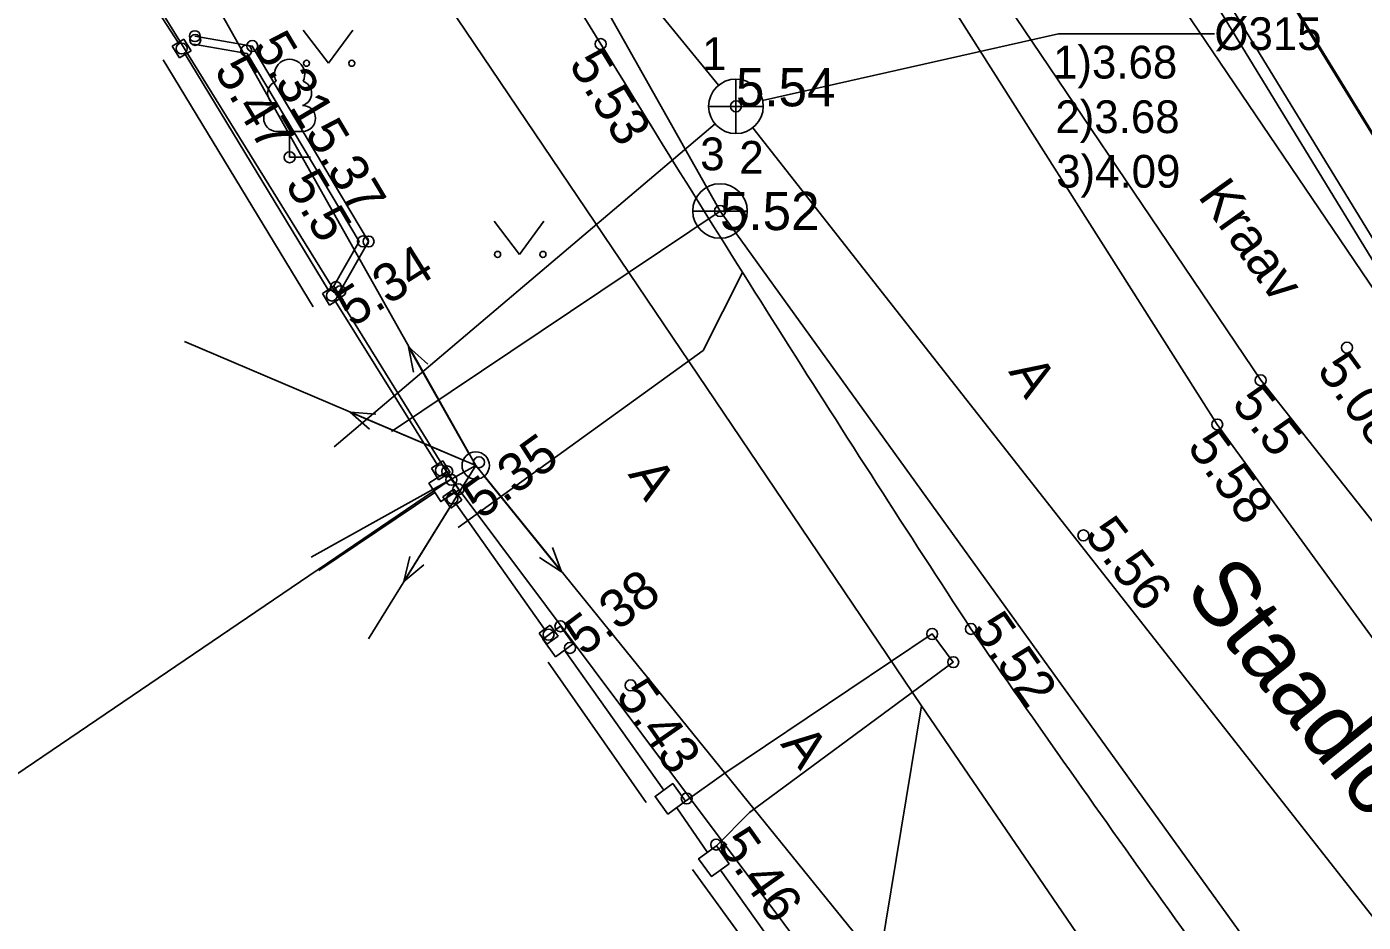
# Model space of a CAD drawing. Extents: x 473307 to 473719, y 6532843 to 6533381.
# Drawn here: x 473422.75 to 473447.22, y 6533044.23 to 6533060.64 of the extents above; entities that cross this region are included whole.
import ezdxf

# ---------------------------------------------------------------- set-up
doc = ezdxf.new("R2010")
doc.units = 0
for name, color, linetype in [('AED', 7, 'Continuous'), ('Default', 7, 'Continuous'), ('HALJASTUS', 7, 'Continuous'), ('KKAEV', 7, 'Continuous'), ('KKAEV_NR', 7, 'Continuous'), ('KORGUS', 7, 'Continuous'), ('KTRASS', 7, 'Continuous'), ('MPKAABEL', 7, 'Continuous'), ('MPOHULIIN', 7, 'Continuous'), ('PIIR', 7, 'Continuous'), ('POST', 7, 'Continuous'), ('PUU', 7, 'Continuous'), ('SITRASS', 7, 'Continuous'), ('TEE', 7, 'Continuous'), ('VEEKOGU', 7, 'Continuous'), ('VKAEV', 7, 'Continuous'), ('VTRASS', 7, 'Continuous')]:
    doc.layers.add(name, color=color, linetype=linetype)

# ---------------------------------------------------------------- blocks, each defined once
blk = doc.blocks.new('KAKAEV')
at = {"layer": 'Default'}
for p, q in [((0, -1), (0, 1)), ((-1, 0), (1, 0))]:
    blk.add_line(p, q, dxfattribs=at)
blk.add_circle((0, 0), 1, dxfattribs=at)
blk = doc.blocks.new('VEKAEV')
at = {"layer": 'Default'}
blk.add_line((-1, 0), (1, 0), dxfattribs=at)
blk.add_circle((0, 0), 1, dxfattribs=at)
blk = doc.blocks.new('PUPOST')
at = {"layer": 'Default'}
blk.add_circle((0, 0), 0.5, dxfattribs=at)
blk = doc.blocks.new('MPSUUN')
at = {"layer": 'Default'}
for p, q in [((0.5, 0), (5, 0)), ((5, 0), (4.097, -0.297)), ((5, 0), (4.098, 0.3))]:
    blk.add_line(p, q, dxfattribs=at)
blk = doc.blocks.new('VARPOS')
at = {"layer": 'Default'}
for p, q in [((-0.25, 0.25), (-0.25, -0.25)), ((-0.25, 0.25), (0.25, 0.25)), ((0.25, 0.25), (0.25, -0.25)), ((-0.25, -0.25), (0.25, -0.25))]:
    blk.add_line(p, q, dxfattribs=at)
blk = doc.blocks.new('LEHTP1')
at = {"layer": 'Default'}
for p, q in [((0.48, 0.95), (-0.48, 0.95)), ((0, 0), (0, 0.95)), ((0.76, 0), (0, 0))]:
    blk.add_line(p, q, dxfattribs=at)
for centre, radius, start, end in [((0, 3.04), 0.554, 332.5799, 207.4201), ((-0.34, 2.345), 0.465, 109.0217, 253.1415), ((0.34, 2.345), 0.465, 286.8508, 70.9859), ((-0.475, 1.425), 0.475, 90.0016, 269.3953), ((0.475, 1.425), 0.475, 270.6047, 89.9984)]:
    blk.add_arc(centre, radius, start, end, dxfattribs=at)
blk = doc.blocks.new('MURU')
at = {"layer": 'Default'}
for p, q in [((-0.927, 1.213), (0, 0)), ((0, 0), (0.891, 1.213))]:
    blk.add_line(p, q, dxfattribs=at)
for centre in [(-0.802, 0), (0.856, 0)]:
    blk.add_circle(centre, 0.11, dxfattribs=at)

msp = doc.modelspace()

# ---------------------------------------------------------------- linework, layer by layer
at = {"layer": 'AED'}
for points in [[(473572.372, 6533059.989), (473562.796, 6533044.25), (473549.715, 6533022.819), (473547.153, 6533018.61), (473538.777, 6533017.059), (473515.614, 6533013.019), (473502.84, 6533010.765), (473486.499, 6533007.9), (473486.322, 6533008.043), (473484.734, 6533009.635), (473455.331, 6533045.745), (473429.609, 6533087.699), (473409.64, 6533128.98), (473398.626, 6533166.806)], [(473425.025, 6533061.109), (473425.519, 6533060.346)], [(473428.268, 6533055.819), (473425.649, 6533060.132)], [(473428.4, 6533055.606), (473430.262, 6533052.618)], [(473430.664, 6533052.156), (473430.447, 6533052.492), (473430.111, 6533052.275), (473430.327, 6533051.939), (473430.664, 6533052.156)], [(473430.219, 6533052.107), (473428.098, 6533050.675)], [(473430.612, 6533051.893), (473432.23, 6533049.604)], [(473432.754, 6533049.332), (473432.52, 6533049.656), (473432.196, 6533049.422), (473432.43, 6533049.098), (473432.754, 6533049.332)], [(473434.415, 6533046.656), (473432.592, 6533049.215)], [(473434.811, 6533046.449), (473434.577, 6533046.773), (473434.253, 6533046.539), (473434.487, 6533046.215), (473434.811, 6533046.449)], [(473434.649, 6533046.332), (473435.214, 6533045.514)], [(473435.61, 6533045.306), (473435.376, 6533045.631), (473435.051, 6533045.397), (473435.285, 6533045.072), (473435.61, 6533045.306)], [(473437.368, 6533042.487), (473435.448, 6533045.189)]]:
    msp.add_lwpolyline(points, dxfattribs=at)
at = {"layer": 'HALJASTUS'}
for points in [[(473427.991, 6533055.504), (473425.242, 6533060.031)], [(473434.087, 6533046.427), (473432.296, 6533048.996)], [(473443.677, 6533033.162), (473434.939, 6533045.198)]]:
    msp.add_lwpolyline(points, dxfattribs=at)
at = {"layer": 'KKAEV_NR'}
msp.add_lwpolyline([(473436.222, 6533059.289), (473441.643, 6533060.51), (473444.495, 6533060.51)], dxfattribs=at)
at = {"layer": 'KORGUS'}
for centre in [(473425.825, 6533060.465), (473425.584, 6533060.239), (473425.832, 6533060.395), (473426.767, 6533060.199), (473426.876, 6533060.284), (473433.257, 6533060.319), (473435.734, 6533059.179), (473427.561, 6533058.246), (473435.442, 6533057.262), (473428.904, 6533056.705), (473429.007, 6533056.703), (473428.408, 6533055.868), (473428.489, 6533055.793), (473428.333, 6533055.712), (473446.923, 6533054.759), (473445.343, 6533054.161), (473444.547, 6533053.352), (473431.029, 6533052.66), (473430.329, 6533052.512), (473430.447, 6533052.492), (473430.522, 6533052.338), (473430.65, 6533052.165), (473430.54, 6533051.995), (473442.097, 6533051.32), (473432.302, 6533049.502), (473432.52, 6533049.656), (473439.327, 6533049.514), (473440.037, 6533049.606), (473432.695, 6533049.259), (473439.714, 6533048.998), (473433.804, 6533048.573), (473434.833, 6533046.501), (473435.371, 6533045.656)]:
    msp.add_circle(centre, 0.1, dxfattribs=at)
at = {"layer": 'KTRASS'}
for p, q in [((473418.47, 6533080.248), (473435.417, 6533059.566)), ((473436.043, 6533058.786), (473462.581, 6533024.994))]:
    msp.add_line(p, q, dxfattribs=at)
msp.add_lwpolyline([(473428.378, 6533052.943), (473435.353, 6533058.856)], dxfattribs=at)
at = {"layer": 'MPKAABEL'}
for points in [[(473481.096, 6533010.082), (473475.299, 6533017.476), (473469.705, 6533025.438), (473464.809, 6533033.306), (473458.878, 6533040.236), (473452.764, 6533048.342), (473452.582, 6533049.145), (473450.829, 6533050.743), (473441.685, 6533065.704), (473432.314, 6533080.211), (473428.426, 6533086.609), (473420.464, 6533103.751), (473416.16, 6533112.695), (473415.168, 6533114.011), (473413.395, 6533118.629), (473406.551, 6533134.777), (473402.712, 6533147.764), (473401.357, 6533149.404), (473399.947, 6533154.634), (473395.886, 6533169.008), (473391.18, 6533184.279)], [(473432.314, 6533080.211), (473441.685, 6533065.704), (473450.829, 6533050.743), (473452.582, 6533049.145)], [(473452.582, 6533049.145), (473450.993, 6533050.878), (473441.863, 6533065.816)]]:
    msp.add_lwpolyline(points, dxfattribs=at)
for points in [[(473512.387, 6533012.718), (473511.709, 6533013.458), (473511.644, 6533013.813), (473511.542, 6533014.613), (473511.381, 6533017.659), (473511.142, 6533020.044), (473510.874, 6533022.048), (473510.569, 6533024.181), (473510.483, 6533025.89), (473510.516, 6533027.894), (473510.641, 6533030.331), (473510.67, 6533031.833), (473510.655, 6533032.119), (473510.649, 6533032.555), (473510.639, 6533032.762), (473510.589, 6533032.95), (473510.316, 6533033.111), (473509.354, 6533033.422), (473507.996, 6533033.86), (473502.455, 6533035.652), (473496.274, 6533037.678), (473490.95, 6533039.423), (473486.411, 6533040.598), (473481.57, 6533041.955), (473473.486, 6533044.266), (473470.456, 6533045.132), (473469.695, 6533045.349), (473468.226, 6533046.487), (473468.095, 6533047.18), (473467.821, 6533048.63), (473467.366, 6533051.035), (473466.864, 6533053.691), (473466.381, 6533056.243), (473466.321, 6533057.471), (473466.418, 6533059.213), (473466.484, 6533060.394), (473467.163, 6533064.378), (473467.581, 6533069.215), (473467.741, 6533070.834), (473467.945, 6533074.093), (473468.112, 6533076.746), (473468.308, 6533079.877), (473468.368, 6533080.827), (473468.195, 6533082.441), (473467.801, 6533084.78), (473466.975, 6533089.686), (473465.432, 6533098.846), (473464.577, 6533103.922), (473462.937, 6533114.557), (473462.089, 6533120.164), (473461.167, 6533124.352), (473460.389, 6533127.622), (473459.684, 6533130.59), (473458.638, 6533134.987), (473457.53, 6533139.179), (473456.93, 6533140.376), (473456.16, 6533141.558), (473454.075, 6533144.132), (473450.58, 6533147.98), (473447.835, 6533151.004), (473446.816, 6533152.126), (473446.343, 6533153.336), (473446.279, 6533153.709), (473445.979, 6533156.453), (473445.694, 6533158.891), (473445.318, 6533162.115), (473444.984, 6533165.254), (473444.88, 6533173.846), (473444.715, 6533176.995), (473444.365, 6533181.379), (473444.303, 6533182.154), (473444.449, 6533184.276), (473444.328, 6533187.274), (473444.133, 6533192.117), (473443.983, 6533195.824), (473443.918, 6533197.679), (473443.848, 6533200.27), (473443.685, 6533203.83), (473443.572, 6533204.805), (473443.351, 6533207.182), (473443.316, 6533207.805), (473443.288, 6533208.471), (473443.754, 6533208.817), (473444.345, 6533208.853), (473445.787, 6533208.941), (473447.513, 6533209.05), (473448.662, 6533209.121), (473453.524, 6533209.424), (473458.616, 6533209.74), (473469.92, 6533210.443), (473477.216, 6533210.896), (473479.911, 6533211.063), (473481.121, 6533211.139), (473481.696, 6533211.355), (473481.884, 6533211.687), (473512.387, 6533012.718), (473481.884, 6533211.687)], [(473557.128, 6533166.896), (473557.202, 6533167.153), (473557.17, 6533167.374), (473557.049, 6533167.727), (473556.952, 6533168.034), (473556.879, 6533168.251), (473556.724, 6533168.7), (473555.529, 6533172.103), (473554.018, 6533176.143), (473551.965, 6533180.794), (473542.001, 6533194.467), (473528.815, 6533203.479), (473521.877, 6533205.787), (473521.549, 6533205.862), (473521.332, 6533205.91), (473521.125, 6533205.955), (473520.94, 6533205.994), (473520.783, 6533206.026), (473520.617, 6533205.983), (473520.549, 6533205.81), (473520.512, 6533205.71), (473520.33, 6533205.301), (473520.277, 6533205.676), (473520.247, 6533205.87), (473520.186, 6533205.982), (473520.155, 6533206.063), (473520.032, 6533206.188), (473519.647, 6533206.25), (473519.297, 6533206.303), (473518.91, 6533206.37), (473518.338, 6533206.457), (473517.785, 6533206.534), (473517.113, 6533206.617), (473504.722, 6533206.361), (473489.125, 6533201.073), (473481.589, 6533195.708), (473477.331, 6533191.94), (473475.034, 6533189.807), (473474.489, 6533189.292), (473474.068, 6533188.932), (473473.832, 6533188.684), (473473.679, 6533188.468), (473473.566, 6533188.217), (473473.476, 6533188.304), (473473.306, 6533188.406), (473473.134, 6533188.531), (473472.969, 6533188.652), (473471.778, 6533189.567), (473469.957, 6533190.966), (473467.155, 6533193.119), (473463.064, 6533196.262), (473458.646, 6533199.657), (473454.573, 6533202.786), (473453.666, 6533203.482), (473453.293, 6533203.769), (473452.995, 6533203.998), (473452.474, 6533204.222), (473452.213, 6533204.228), (473451.967, 6533204.234), (473451.474, 6533204.245), (473450.255, 6533204.273), (473449.394, 6533204.293), (473448.978, 6533204.302), (473448.578, 6533204.312), (473448.301, 6533204.318), (473447.638, 6533204.311), (473446.313, 6533204.297), (473445.312, 6533204.286), (473443.932, 6533204.272), (473441.622, 6533204.247), (473436.282, 6533204.191), (473430.619, 6533203.804), (473423.016, 6533203.284), (473416.174, 6533202.8), (473411.7, 6533202.424), (473406.989, 6533202.027), (473406.298, 6533201.969), (473405.901, 6533201.936), (473405.663, 6533201.916), (473405.247, 6533201.618), (473405.511, 6533201.478), (473405.706, 6533201.471), (473405.859, 6533201.485), (473406.073, 6533201.505), (473406.3, 6533201.526), (473406.699, 6533201.563), (473407.182, 6533201.607), (473407.617, 6533201.647), (473410.794, 6533201.939), (473414.597, 6533202.289), (473416.16, 6533202.433), (473416.748, 6533202.487), (473416.992, 6533202.509), (473417.116, 6533202.479), (473417.282, 6533202.408), (473417.308, 6533202.242), (473417.347, 6533201.989), (473417.396, 6533201.677), (473417.449, 6533201.337), (473417.509, 6533200.949), (473418.04, 6533197.53), (473418.813, 6533192.552), (473421.708, 6533179.543), (473422.341, 6533175.512), (473423.507, 6533169.632), (473424, 6533167.141), (473424.184, 6533166.215), (473424.244, 6533165.909), (473424.294, 6533165.662), (473424.314, 6533165.561), (473424.105, 6533164.865), (473423.816, 6533164.809), (473423.525, 6533164.753), (473422.668, 6533164.588), (473418.846, 6533164.247), (473414.425, 6533164.061), (473411.47, 6533164.651), (473411.357, 6533164.673), (473410.881, 6533164.787), (473410.433, 6533164.888), (473409.953, 6533164.731), (473409.752, 6533164.287), (473409.631, 6533163.669), (473409.502, 6533157.703), (473410.074, 6533152.735), (473410.969, 6533148.729), (473415.098, 6533136.501), (473416.702, 6533131.364), (473421.711, 6533117.606), (473423.352, 6533113.701), (473430.005, 6533097.933), (473437.623, 6533088.588), (473441.02, 6533084.73), (473450.501, 6533069.242), (473457.775, 6533058.053), (473462.215, 6533052.558), (473465.73, 6533047.735), (473467.401, 6533046.054), (473469.034, 6533044.411), (473472.353, 6533043.145), (473481.411, 6533040.582), (473489.023, 6533038.632), (473491.007, 6533038.103), (473491.686, 6533037.936), (473492.014, 6533037.852), (473492.476, 6533037.76), (473492.806, 6533038.095), (473492.829, 6533038.485), (473492.856, 6533039.18), (473492.795, 6533042.335), (473492.716, 6533044.024), (473492.683, 6533044.743), (473492.671, 6533044.987), (473492.823, 6533045.601), (473492.984, 6533045.289), (473492.985, 6533045.105), (473493.028, 6533044.585), (473493.105, 6533042.767), (473493.222, 6533039.506), (473493.206, 6533038.15), (473493.196, 6533038.01), (473493.2, 6533037.815), (473493.516, 6533037.437), (473493.94, 6533037.314), (473494.338, 6533037.204), (473496.451, 6533036.58), (473497.497, 6533036.067), (473498.11, 6533035.695), (473498.481, 6533035.454), (473498.784, 6533035.294), (473499.155, 6533035.524), (473499.568, 6533035.786), (473499.965, 6533035.642), (473500.381, 6533035.468), (473500.664, 6533035.366), (473501.255, 6533035.156), (473502.131, 6533034.826), (473503.015, 6533034.496), (473504.909, 6533033.785), (473507.281, 6533033.099), (473509.703, 6533032.392), (473510.465, 6533032.171), (473510.886, 6533032.05), (473511.297, 6533031.932), (473511.665, 6533031.668), (473511.711, 6533031.312), (473511.692, 6533030.835), (473511.632, 6533029.982), (473511.533, 6533028.937), (473511.486, 6533028.283), (473511.407, 6533027.141), (473511.358, 6533026.503), (473511.358, 6533025.257), (473511.617, 6533023.934), (473511.536, 6533023.5), (473511.414, 6533022.901), (473511.43, 6533022.205), (473511.677, 6533020.728), (473511.888, 6533019.916), (473512.37, 6533017.914), (473512.52, 6533015.831), (473512.626, 6533013.709), (473512.595, 6533013.242), (473512.387, 6533012.718), (473557.128, 6533166.896), (473512.387, 6533012.718)]]:
    msp.add_open_spline(points, degree=3, dxfattribs=at)
at = {"layer": 'MPOHULIIN'}
for points in [[(473423.194, 6533272.897), (473391.791, 6533270.484), (473361.09, 6533267.919), (473364.229, 6533220.925), (473380.477, 6533175.317), (473396.165, 6533131.758), (473413.567, 6533083.532), (473430.968, 6533052.6), (473459.84, 6533016.944), (473493.252, 6532975.715), (473524.159, 6532957.128), (473561.498, 6532934.712), (473599.705, 6532914.54), (473648.184, 6532910.183)], [(473430.968, 6533052.6), (473425.638, 6533054.869)], [(473430.968, 6533052.6), (473429.007, 6533049.428)]]:
    msp.add_lwpolyline(points, dxfattribs=at)
at = {"layer": 'PIIR'}
for points in [[(473383.26, 6533220.83), (473372.23, 6533259.41), (473496.37, 6533266.79), (473499.84, 6533206.38), (473559.2, 6533209.37), (473561.43, 6533165.2), (473601.75, 6533167.04), (473607.56, 6533132.38), (473611.09, 6533109.85), (473618.6, 6533063.82), (473572.63, 6533056.43), (473548.5, 6533028.91), (473478.82, 6533017), (473455.33, 6533045.76), (473432.18, 6533083.36), (473429.59, 6533087.74), (473409.64, 6533129), (473385.1, 6533214.25), (473398.68, 6533216.8), (473398.11, 6533224.3)], [(473389.01, 6533059.81), (473416.35, 6533075.22), (473430.52, 6533052.35), (473405.34, 6533035.25)], [(473405.34, 6533035.25), (473430.52, 6533052.35), (473444.45, 6533033.74), (473419.4, 6533015.03)]]:
    msp.add_lwpolyline(points, close=True, dxfattribs=at)
for points in [[(473385.1, 6533214.25), (473409.64, 6533129), (473429.59, 6533087.74), (473432.18, 6533083.36), (473455.33, 6533045.76), (473478.82, 6533017)], [(473492.55, 6532977.62), (473473.12, 6532997.79), (473458.1, 6533015.44), (473444.45, 6533033.74), (473430.52, 6533052.35), (473416.35, 6533075.22), (473412.06, 6533083.41), (473400.27, 6533108.71), (473390.77, 6533130.51), (473383.02, 6533152.56), (473376.06, 6533174.78), (473369.76, 6533197.52)]]:
    msp.add_lwpolyline(points, dxfattribs=at)
at = {"layer": 'POST'}
msp.add_line((473427.954, 6533050.92), (473430.968, 6533052.6), dxfattribs=at)
at = {"layer": 'SITRASS'}
msp.add_line((473439.13, 6533048.2), (473437.918, 6533040.86), dxfattribs=at)
msp.add_lwpolyline([(473410.951, 6533089.791), (473424.02, 6533070.59), (473439.13, 6533048.2), (473447.57, 6533035.84), (473453.172, 6533027.457)], dxfattribs=at)
at = {"layer": 'TEE'}
for points in [[(473486.74, 6533007.668), (473486.486, 6533007.568), (473485.836, 6533006.833), (473483.72, 6533004.961), (473480.798, 6533008.092), (473475.573, 6533014.142), (473470.165, 6533020.489), (473464.659, 6533026.983), (473458.607, 6533034.554), (473452.151, 6533042.899), (473444.547, 6533053.352), (473438.634, 6533062.682), (473435.33, 6533068.051), (473426.278, 6533084.212), (473422.195, 6533091.615), (473414.542, 6533107.225), (473409.577, 6533117.788), (473405.358, 6533127.822), (473401.846, 6533136.79), (473397.087, 6533149.814), (473394.968, 6533156.469), (473393.12, 6533161.978)], [(473423.219, 6533077.195), (473430.356, 6533065.049), (473433.257, 6533060.319)], [(473428.359, 6533055.867), (473428.833, 6533056.701), (473426.782, 6533060.148), (473425.8, 6533060.317)], [(473428.489, 6533055.793), (473429.007, 6533056.703), (473426.876, 6533060.284), (473425.825, 6533060.465)], [(473430.65, 6533051.465), (473435.133, 6533054.704), (473435.854, 6533056.136)], [(473434.811, 6533046.449), (473435.509, 6533046.951), (473439.327, 6533049.514), (473439.714, 6533048.998), (473435.983, 6533046.246), (473435.376, 6533045.631)]]:
    msp.add_lwpolyline(points, dxfattribs=at)
for centre, radius, start, end in [((473816.857, 6533295.588), 450, 211.52159, 213.13588), ((473800.251, 6533299.533), 438.427, 214.75406, 216.40059)]:
    msp.add_arc(centre, radius, start, end, dxfattribs=at)
at = {"layer": 'VEEKOGU'}
for points in [[(473402.6, 6533145.241), (473405.051, 6533138.423), (473408.63, 6533128.571), (473412.37, 6533119.672), (473415.881, 6533111.58), (473424.05, 6533094.363), (473432.068, 6533080.056), (473438.112, 6533070.078), (473441.876, 6533064.003), (473447.577, 6533055.58), (473453.746, 6533046.091)], [(473452.326, 6533045.335), (473445.343, 6533054.161), (473439.616, 6533062.658), (473436.096, 6533068.575), (473429.941, 6533078.645), (473422.233, 6533093.292), (473413.911, 6533110.283), (473410.493, 6533118.237), (473406.183, 6533128.288), (473402.792, 6533137.828), (473400.309, 6533144.749)]]:
    msp.add_lwpolyline(points, dxfattribs=at)
at = {"layer": 'VTRASS'}
msp.add_line((473429.425, 6533053.222), (473435.442, 6533057.262), dxfattribs=at)
msp.add_lwpolyline([(473365.999, 6533272.186), (473364.518, 6533257.871), (473366.737, 6533240.392), (473372.861, 6533211.206), (473381.92, 6533180.915), (473385.845, 6533164.961), (473390.472, 6533150.34), (473401.875, 6533121.622), (473409.867, 6533103.775), (473420.281, 6533084.249), (473435.442, 6533057.262), (473447.562, 6533040.443), (473454.221, 6533030.196), (473471.046, 6533010.477), (473501.071, 6532979.442)], dxfattribs=at)

# ---------------------------------------------------------------- block references
at = {"layer": 'AED'}
for p, xscale, yscale, rotation in [((473425.584, 6533060.239), 0.5000000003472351, 0.5, 121.38201121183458), ((473428.333, 6533055.712), 0.5000000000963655, 0.5, -57.793736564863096), ((473430.329, 6533052.512), 0.5000000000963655, 0.5, -57.793736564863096), ((473430.54, 6533051.995), 0.5000000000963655, 0.4999999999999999, -54.748133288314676), ((473432.302, 6533049.502), 0.5000000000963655, 0.4999999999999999, -54.748133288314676)]:
    msp.add_blockref('VARPOS', p, dxfattribs=dict(at, xscale=xscale, yscale=yscale, rotation=rotation))
at = {"layer": 'HALJASTUS', "xscale": 0.5, "yscale": 0.5}
for p in [(473428.271, 6533059.967), (473431.771, 6533056.467)]:
    msp.add_blockref('MURU', p, dxfattribs=at)
at = {"layer": 'KKAEV', "xscale": 0.5, "yscale": 0.5}
msp.add_blockref('KAKAEV', (473435.734, 6533059.179), dxfattribs=at)
at = {"layer": 'MPOHULIIN'}
for xscale, yscale, rotation in [(0.49999999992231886, 0.5, 119.45008980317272), (0.5000000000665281, 0.5, 156.94228940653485), (0.500000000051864, 0.5, -121.72165657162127), (0.499999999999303, 0.49999999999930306, -51.09676311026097)]:
    msp.add_blockref('MPSUUN', (473430.968, 6533052.6), dxfattribs=dict(at, xscale=xscale, yscale=yscale, rotation=rotation))
at = {"layer": 'POST', "xscale": 0.5, "yscale": 0.5}
msp.add_blockref('PUPOST', (473430.968, 6533052.6), dxfattribs=at)
at = {"layer": 'PUU', "xscale": 0.5, "yscale": 0.5}
msp.add_blockref('LEHTP1', (473427.561, 6533058.246), dxfattribs=at)
at = {"layer": 'VKAEV', "xscale": 0.5, "yscale": 0.5}
msp.add_blockref('VEKAEV', (473435.442, 6533057.262), dxfattribs=at)

# ---------------------------------------------------------------- texts
at = {"layer": 'KKAEV_NR'}
for s, p in [('%%c315', (473444.495, 6533060.21)), ('1', (473435.113, 6533059.842)), ('1)3.68', (473441.54, 6533059.689)), ('2)3.68', (473441.583, 6533058.689)), ('3', (473435.079, 6533058.008)), ('2', (473435.795, 6533057.945)), ('3)4.09', (473441.598, 6533057.689))]:
    msp.add_text(s, height=0.6, dxfattribs=at).set_placement(p)
at = {"layer": 'KORGUS'}
for s, rotation, p in [('5.31', 300.7562, (473426.876, 6533060.284)), ('5.47', 300.7562, (473426.165, 6533059.841)), ('5.53', 301.6269, (473432.661, 6533059.952)), ('5.37', 300.7562, (473427.828, 6533058.685)), ('5.5', 300.7562, (473427.467, 6533057.751)), ('5.34', 32.114, (473428.705, 6533055.119)), ('5.08', 306.0792, (473446.357, 6533054.347)), ('5.5', 308.3505, (473444.794, 6533053.727)), ('5.58', 306.0339, (473443.981, 6533052.94)), ('5.35', 35.833, (473431.06, 6533051.597)), ('5.56', 307.8789, (473442.097, 6533051.32)), ('5.38', 36.5916, (473432.937, 6533049.094)), ('5.52', 304.9289, (473440.037, 6533049.606)), ('5.43', 304.8902, (473433.517, 6533048.388)), ('5.46', 305.3905, (473435.371, 6533045.656))]:
    msp.add_text(s, height=0.7, rotation=rotation, dxfattribs=at).set_placement(p)
for s, p in [('5.54', (473435.734, 6533059.179)), ('5.52', (473435.442, 6533056.912))]:
    msp.add_text(s, height=0.7, dxfattribs=at).set_placement(p)
at = {"layer": 'TEE'}
for s, height, rotation, p in [('A', 0.7, 302.2555, (473440.715, 6533054.319)), ('A', 0.7, 303.22, (473433.746, 6533052.437)), ('Staadioni tn', 1.2, 308.8658, (473443.924, 6533050.296)), ('A', 0.7, 307.4648, (473436.537, 6533047.494))]:
    msp.add_text(s, height=height, rotation=rotation, dxfattribs=at).set_placement(p)
at = {"layer": 'VEEKOGU'}
msp.add_text('Kraav', height=0.7, rotation=305.6537, dxfattribs=at).set_placement((473444.179, 6533057.53))

doc.saveas('drawing.dxf')
